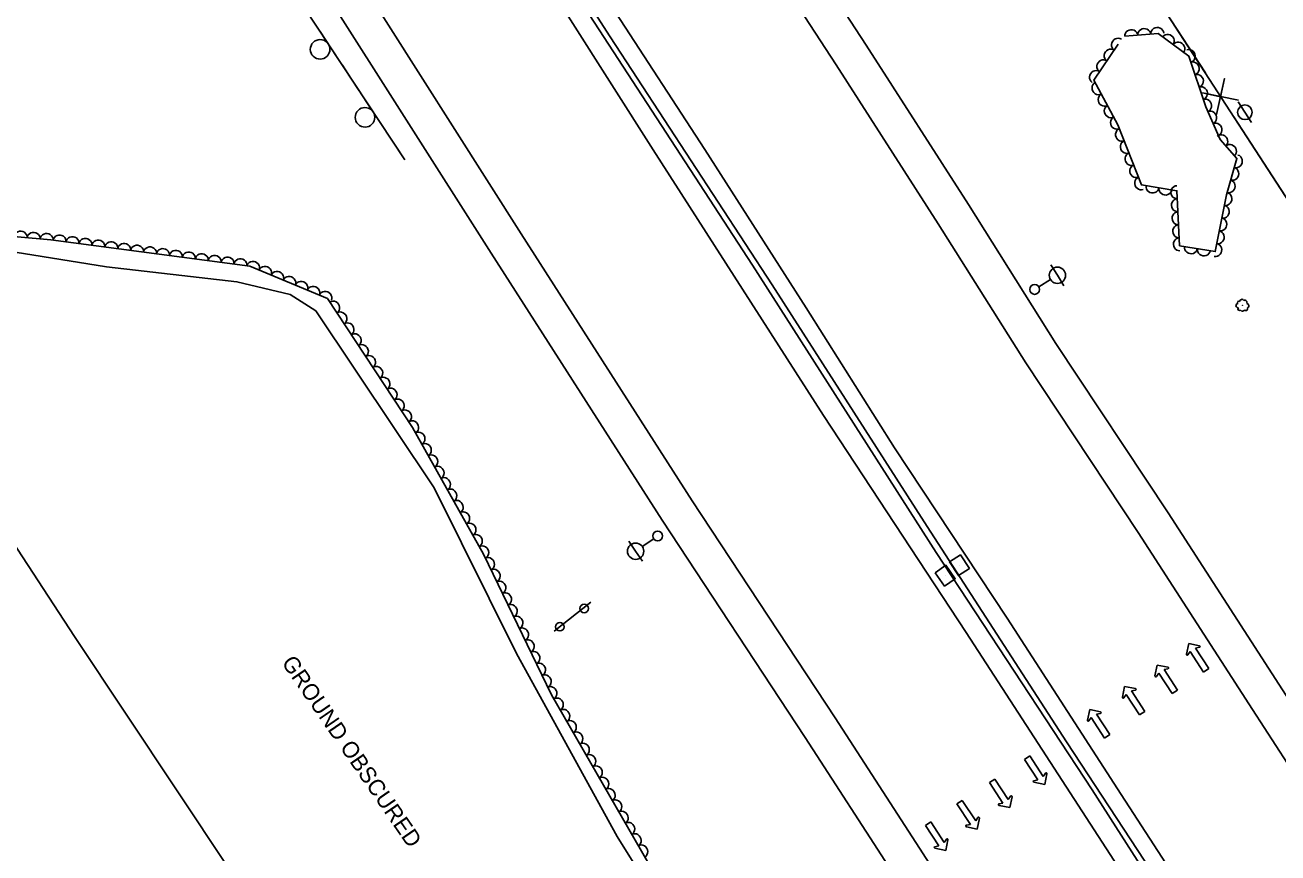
# Model space of a CAD drawing. Extents: x 1746719 to 1766531, y 631721 to 662391.
# Drawn here: x 1759684.8 to 1760069.2, y 641498.8 to 641752.7 of the extents above; entities that cross this region are included whole.
import ezdxf

# ---------------------------------------------------------------- set-up
doc = ezdxf.new("R2010")
doc.units = 0
for name, color, linetype in [('SURVEY - AERIAL SURVEY - Photo Control - Points - Elevations', 7, 'Continuous'), ('SURVEY - AERIAL SURVEY - Photo Control - Points - Locators', 7, 'Continuous'), ('SURVEY - AERIAL SURVEY - Photo Control - Points - Numbers', 7, 'Continuous'), ('SURVEY - AERIAL SURVEY - Photo Control with Text', 7, 'Continuous'), ('SURVEY - CENTERLINE - Existing Roads - Development', 7, 'Continuous'), ('SURVEY - CENTERLINE - Existing Roads Curve Text', 7, 'Continuous'), ('SURVEY - CENTERLINE - Preliminary Curve Text', 7, 'Continuous'), ('SURVEY - CONTROL - Grid', 7, 'Continuous')]:
    doc.layers.add(name, color=color, linetype=linetype)

msp = doc.modelspace()

# ---------------------------------------------------------------- linework, layer by layer
at = {"layer": 'SURVEY - AERIAL SURVEY - Photo Control - Points - Elevations'}
for points in [[(1759256.28, 642562.06), (1759331.34, 642448.21), (1759372.09, 642386.38), (1759428.32, 642299.79), (1759481.08, 642217.88), (1759538.71, 642129.24), (1759603.54, 642028.16), (1759659.74, 641942.25), (1759711.51, 641861.77), (1759776.52, 641763.39), (1759827.75, 641682.76), (1759880.28, 641600.83), (1759924.14, 641534.16), (1759977.94, 641451.1), (1760016.39, 641391.3), (1760062.96, 641319.36), (1760103.56, 641256.45), (1760143.11, 641194.73), (1760191.91, 641118.87), (1760244.47, 641040.54), (1760278.02, 640988.87), (1760344.17, 640886.4)], [(1759271.68, 642558.69), (1759340.52, 642454.26), (1759381.29, 642392.41), (1759437.55, 642305.76), (1759490.31, 642223.86), (1759547.95, 642135.2), (1759612.77, 642034.14), (1759668.97, 641948.23), (1759720.72, 641867.78), (1759785.75, 641769.38), (1759837.02, 641688.68), (1759889.51, 641606.82), (1759933.35, 641540.17), (1759987.18, 641457.06), (1760025.63, 641397.26), (1760072.2, 641325.33), (1760112.81, 641262.4), (1760152.37, 641200.67), (1760201.11, 641124.91), (1760253.65, 641046.61), (1760287.26, 640994.85), (1760353.41, 640892.37)], [(1759339.73, 642542.67), (1759380.59, 642480.68), (1759421.46, 642418.69), (1759477.86, 642331.83), (1759530.61, 642249.94), (1759588.28, 642161.24), (1759653.06, 642060.23), (1759709.23, 641974.36), (1759760.93, 641894), (1759826.04, 641795.48), (1759877.48, 641714.5), (1759929.76, 641632.96), (1759973.54, 641566.41), (1760027.51, 641483.09), (1760065.96, 641423.28), (1760112.51, 641351.39), (1760153.19, 641288.36), (1760192.76, 641226.6), (1760241.22, 641151.27), (1760293.71, 641073.05), (1760327.55, 641020.94), (1760393.74, 640918.4)], [(1759649.07, 642091.68), (1759686.79, 642032.95), (1759716.7, 641987.2), (1759751.66, 641932.46), (1759795.99, 641863.79), (1759827.24, 641815.11), (1759866.04, 641756.45), (1759893.31, 641714.53), (1759924.46, 641666), (1759951.54, 641623.05), (1759986.16, 641570.79), (1760021.11, 641516.73), (1760049.81, 641472.4), (1760081.63, 641423.88), (1760117.03, 641367.86), (1760151.23, 641315.54), (1760184.39, 641264.09), (1760220.08, 641208.95), (1760253.71, 641157.15), (1760284.42, 641109.9), (1760319.58, 641055.54), (1760351.26, 641006.23), (1760381.49, 640960.02), (1760404.24, 640925.21)], [(1759915.38, 641788.81), (1759942.87, 641746.55), (1759974.24, 641697.67), (1760001.09, 641655.07), (1760035.52, 641603.1), (1760070.64, 641548.78), (1760099.24, 641504.61), (1760131.24, 641455.82), (1760166.66, 641399.76), (1760200.72, 641347.67), (1760233.95, 641296.1), (1760269.59, 641241.05), (1760303.18, 641189.29), (1760333.92, 641142), (1760369.17, 641087.5), (1760400.77, 641038.33), (1760430.87, 640992.31), (1760453.63, 640957.5)], [(1759906.18, 641782.77), (1759933.63, 641740.58), (1759964.96, 641691.76), (1759991.85, 641649.1), (1760026.32, 641597.07), (1760061.41, 641542.8), (1760090.03, 641498.61), (1760121.99, 641449.86), (1760157.41, 641393.81), (1760191.49, 641341.68), (1760224.71, 641290.14), (1760260.36, 641235.06), (1760293.96, 641183.3), (1760324.69, 641136.02), (1760359.93, 641081.54), (1760391.54, 641032.35), (1760421.66, 640986.29), (1760444.42, 640951.48)]]:
    msp.add_lwpolyline(points, dxfattribs=at)
at = {"layer": 'SURVEY - AERIAL SURVEY - Photo Control - Points - Locators'}
for p, q in [((1760041.12, 641559.7), (1760041.81, 641563.01)), ((1760041.81, 641563.01), (1760041.12, 641559.7)), ((1760041.81, 641563.01), (1760045.11, 641562.32)), ((1760041.81, 641563.01), (1760045.11, 641562.32)), ((1760045.11, 641561.84), (1760043.9, 641561.61)), ((1760043.9, 641561.61), (1760045.11, 641561.84)), ((1760043.9, 641561.61), (1760048.03, 641555.32)), ((1760048.03, 641555.32), (1760043.9, 641561.61)), ((1760042.26, 641560.53), (1760041.56, 641559.51)), ((1760042.26, 641560.53), (1760041.56, 641559.51)), ((1760046.38, 641554.24), (1760042.26, 641560.53)), ((1760046.38, 641554.24), (1760042.26, 641560.53)), ((1760031.47, 641553.1), (1760032.16, 641556.41)), ((1760032.16, 641556.41), (1760031.47, 641553.1)), ((1760032.61, 641553.93), (1760031.92, 641552.91)), ((1760032.61, 641553.93), (1760031.92, 641552.91)), ((1760032.16, 641556.41), (1760035.47, 641555.72)), ((1760032.16, 641556.41), (1760035.47, 641555.72)), ((1760036.73, 641547.64), (1760032.61, 641553.93)), ((1760036.73, 641547.64), (1760032.61, 641553.93)), ((1760035.46, 641555.24), (1760034.25, 641555.01)), ((1760034.25, 641555.01), (1760035.46, 641555.24)), ((1760034.25, 641555.01), (1760038.38, 641548.72)), ((1760038.38, 641548.72), (1760034.25, 641555.01)), ((1760048.03, 641555.32), (1760046.38, 641554.24)), ((1760046.38, 641554.24), (1760048.03, 641555.32)), ((1760021.46, 641546.54), (1760022.15, 641549.84)), ((1760022.15, 641549.84), (1760021.46, 641546.54)), ((1760022.6, 641547.37), (1760021.91, 641546.35)), ((1760022.6, 641547.37), (1760021.91, 641546.35)), ((1760022.15, 641549.84), (1760025.46, 641549.16)), ((1760022.15, 641549.84), (1760025.46, 641549.16)), ((1760026.72, 641541.08), (1760022.6, 641547.37)), ((1760026.72, 641541.08), (1760022.6, 641547.37)), ((1760025.45, 641548.68), (1760024.24, 641548.45)), ((1760024.24, 641548.45), (1760025.45, 641548.68)), ((1760024.24, 641548.45), (1760028.37, 641542.16)), ((1760028.37, 641542.16), (1760024.24, 641548.45)), ((1760038.38, 641548.72), (1760036.73, 641547.64)), ((1760036.73, 641547.64), (1760038.38, 641548.72)), ((1760010.75, 641539.45), (1760011.44, 641542.75)), ((1760011.44, 641542.75), (1760010.75, 641539.45)), ((1760011.44, 641542.75), (1760014.75, 641542.06)), ((1760011.44, 641542.75), (1760014.75, 641542.06)), ((1760011.89, 641540.27), (1760011.2, 641539.26)), ((1760011.89, 641540.27), (1760011.2, 641539.26)), ((1760016.01, 641533.98), (1760011.89, 641540.27)), ((1760016.01, 641533.98), (1760011.89, 641540.27)), ((1760014.74, 641541.58), (1760013.53, 641541.35)), ((1760013.53, 641541.35), (1760014.74, 641541.58)), ((1760013.53, 641541.35), (1760017.66, 641535.06)), ((1760017.66, 641535.06), (1760013.53, 641541.35)), ((1760028.37, 641542.16), (1760026.72, 641541.08)), ((1760026.72, 641541.08), (1760028.37, 641542.16)), ((1760017.66, 641535.06), (1760016.01, 641533.98)), ((1760016.01, 641533.98), (1760017.66, 641535.06)), ((1759991.42, 641527.44), (1759993.06, 641528.52)), ((1759993.06, 641528.52), (1759991.42, 641527.44)), ((1759995.54, 641521.15), (1759991.42, 641527.44)), ((1759991.42, 641527.44), (1759995.54, 641521.15)), ((1759993.06, 641528.52), (1759997.19, 641522.23)), ((1759993.06, 641528.52), (1759997.19, 641522.23)), ((1759997.19, 641522.23), (1759997.88, 641523.25)), ((1759997.19, 641522.23), (1759997.88, 641523.25)), ((1759998.32, 641523.06), (1759997.63, 641519.75)), ((1759997.63, 641519.75), (1759998.32, 641523.06)), ((1759980.7, 641520.35), (1759982.35, 641521.43)), ((1759982.35, 641521.43), (1759980.7, 641520.35)), ((1759984.83, 641514.06), (1759980.7, 641520.35)), ((1759980.7, 641520.35), (1759984.83, 641514.06)), ((1759982.35, 641521.43), (1759986.47, 641515.14)), ((1759982.35, 641521.43), (1759986.47, 641515.14)), ((1759994.33, 641520.92), (1759995.54, 641521.15)), ((1759995.54, 641521.15), (1759994.33, 641520.92)), ((1759997.63, 641519.75), (1759994.33, 641520.44)), ((1759997.63, 641519.75), (1759994.33, 641520.44)), ((1759986.47, 641515.14), (1759987.17, 641516.15)), ((1759986.47, 641515.14), (1759987.17, 641516.15)), ((1759987.61, 641515.96), (1759986.92, 641512.66)), ((1759986.92, 641512.66), (1759987.61, 641515.96)), ((1759970.69, 641513.78), (1759972.34, 641514.86)), ((1759972.34, 641514.86), (1759970.69, 641513.78)), ((1759974.82, 641507.49), (1759970.69, 641513.78)), ((1759970.69, 641513.78), (1759974.82, 641507.49)), ((1759972.34, 641514.86), (1759976.46, 641508.57)), ((1759972.34, 641514.86), (1759976.46, 641508.57)), ((1759983.62, 641513.83), (1759984.83, 641514.06)), ((1759984.83, 641514.06), (1759983.62, 641513.83)), ((1759986.92, 641512.66), (1759983.62, 641513.35)), ((1759986.92, 641512.66), (1759983.62, 641513.35)), ((1759961.04, 641507.19), (1759962.69, 641508.27)), ((1759962.69, 641508.27), (1759961.04, 641507.19)), ((1759962.69, 641508.27), (1759966.81, 641501.98)), ((1759962.69, 641508.27), (1759966.81, 641501.98)), ((1759976.46, 641508.57), (1759977.16, 641509.59)), ((1759976.46, 641508.57), (1759977.16, 641509.59)), ((1759977.6, 641509.4), (1759976.91, 641506.09)), ((1759976.91, 641506.09), (1759977.6, 641509.4)), ((1759965.17, 641500.9), (1759961.04, 641507.19)), ((1759961.04, 641507.19), (1759965.17, 641500.9)), ((1759973.61, 641507.26), (1759974.82, 641507.49)), ((1759974.82, 641507.49), (1759973.61, 641507.26)), ((1759976.91, 641506.09), (1759973.61, 641506.78)), ((1759976.91, 641506.09), (1759973.61, 641506.78)), ((1759963.96, 641500.67), (1759965.17, 641500.9)), ((1759965.17, 641500.9), (1759963.96, 641500.67)), ((1759967.26, 641499.5), (1759963.96, 641500.19)), ((1759967.26, 641499.5), (1759963.96, 641500.19)), ((1759966.81, 641501.98), (1759967.51, 641502.99)), ((1759966.81, 641501.98), (1759967.51, 641502.99)), ((1759967.95, 641502.81), (1759967.26, 641499.5)), ((1759967.26, 641499.5), (1759967.95, 641502.81))]:
    msp.add_line(p, q, dxfattribs=at)
for points in [[(1759661.89, 641686.19), (1759709.71, 641678.57), (1759749.78, 641673.99), (1759766.09, 641670.05), (1759774.03, 641665.09)], [(1759910.32, 641247.02), (1759855.72, 641330.61), (1759778.79, 641446.62), (1759699.92, 641565.14), (1759631.39, 641669.95)], [(1759774.03, 641665.09), (1759810.29, 641610.78), (1759835.53, 641559.97), (1759866.48, 641503.82), (1759905.29, 641441.52), (1759936.98, 641392.21), (1759970.33, 641331.59), (1759997.67, 641284.96)]]:
    msp.add_lwpolyline(points, dxfattribs=at)
for centre, start, end in [((1760045.07, 641562.08), 280.8054, 78.2537), ((1760045.07, 641562.08), 280.8054, 78.2537), ((1760041.36, 641559.65), 168.2537, 325.7468), ((1760041.36, 641559.65), 168.2537, 325.7468), ((1760035.42, 641555.48), 280.8054, 78.2537), ((1760035.42, 641555.48), 280.8054, 78.2537), ((1760031.71, 641553.05), 168.2537, 325.7468), ((1760031.71, 641553.05), 168.2537, 325.7468), ((1760021.7, 641546.49), 168.2537, 325.7468), ((1760021.7, 641546.49), 168.2537, 325.7468), ((1760025.41, 641548.92), 280.8054, 78.2537), ((1760025.41, 641548.92), 280.8054, 78.2537), ((1760010.99, 641539.4), 168.2537, 325.7468), ((1760010.99, 641539.4), 168.2537, 325.7468), ((1760014.69, 641541.82), 280.8054, 78.2537), ((1760014.69, 641541.82), 280.8054, 78.2537), ((1759998.08, 641523.11), 348.2537, 145.7468), ((1759998.08, 641523.11), 348.2537, 145.7468), ((1759994.38, 641520.68), 100.8054, 258.2537), ((1759994.38, 641520.68), 100.8054, 258.2537), ((1759987.37, 641516.02), 348.2537, 145.7468), ((1759987.37, 641516.02), 348.2537, 145.7468), ((1759983.67, 641513.59), 100.8054, 258.2537), ((1759983.67, 641513.59), 100.8054, 258.2537), ((1759977.36, 641509.45), 348.2537, 145.7468), ((1759977.36, 641509.45), 348.2537, 145.7468), ((1759973.66, 641507.02), 100.8054, 258.2537), ((1759973.66, 641507.02), 100.8054, 258.2537), ((1759964.01, 641500.43), 100.8054, 258.2537), ((1759964.01, 641500.43), 100.8054, 258.2537), ((1759967.71, 641502.86), 348.2537, 145.7468), ((1759967.71, 641502.86), 348.2537, 145.7468)]:
    msp.add_arc(centre, 0.246, start, end, dxfattribs=at)
at = {"layer": 'SURVEY - AERIAL SURVEY - Photo Control - Points - Numbers'}
for points in [[(1759345.56, 642540.12), (1759369.43, 642507.42), (1759376.29, 642498.78), (1759406.04, 642453.59), (1759456.4, 642376.16), (1759516.08, 642283.87), (1759556.82, 642220.43), (1759597.59, 642157.91), (1759654.19, 642071.42), (1759714.99, 641977.18), (1759758.52, 641910), (1759805.91, 641836.88), (1759854.97, 641760.37), (1759907.97, 641679.1), (1759964.38, 641590.9), (1760012.24, 641518.09), (1760081.05, 641410.57), (1760126.05, 641341.92), (1760170.81, 641272.63), (1760237.12, 641169.73), (1760281.11, 641102.87), (1760319.96, 641040.85), (1760359.87, 640980.23), (1760396.33, 640923.21)], [(1759643.49, 642091.23), (1759685.97, 642024.92), (1759725.12, 641963.78), (1759767.21, 641899.68), (1759813.02, 641828.86), (1759864.29, 641749.12), (1759913.96, 641673.03), (1759961.57, 641598.93), (1760004.36, 641532.83), (1760058.79, 641449.82), (1760104.5, 641378.48), (1760159.43, 641293.11), (1760200.94, 641229.52), (1760246.07, 641159.36), (1760287.63, 641096.04), (1760327.89, 641032.95), (1760362.68, 640979.45), (1760398.55, 640924.9)], [(1759593.21, 642029.44), (1759596.82, 642023.81), (1759653.03, 641937.89), (1759704.81, 641857.4), (1759801.29, 641711.41)], [(1759775.29, 641750.75), (1759780.36, 641743.07)], [(1759782.13, 641740.4), (1759784.72, 641736.48)], [(1759784.72, 641736.48), (1759787.31, 641732.56)], [(1759789.07, 641729.89), (1759794.15, 641722.21)], [(1759795.91, 641719.54), (1759798.5, 641715.62)], [(1759798.5, 641715.62), (1759801.09, 641711.7)]]:
    msp.add_lwpolyline(points, dxfattribs=at)
for centre in [(1759775.3, 641745.29), (1759789.08, 641724.44)]:
    msp.add_arc(centre, 3, 146.7274, 146.7134, dxfattribs=at)
at = {"layer": 'SURVEY - AERIAL SURVEY - Photo Control with Text'}
for points in [[(1760022.19, 641749.29), (1760032.4, 641750.13), (1760041.9, 641743.24), (1760047.07, 641727.62), (1760051.44, 641717.65), (1760056.62, 641711.78), (1760053.4, 641700.66), (1760049.97, 641683.27), (1760039.03, 641685.03), (1760038.21, 641701.9), (1760027.32, 641703.68), (1760020.07, 641722.1), (1760012.69, 641735.89), (1760020.19, 641746.93)], [(1759663.03, 641689.47), (1759692.72, 641686.81), (1759753.75, 641678.76), (1759777.55, 641668.87), (1759803.65, 641629.31), (1759825.45, 641590.41), (1759846.33, 641547.25), (1759884, 641481.67), (1759907.38, 641444.09), (1759941.32, 641392.48), (1759962.01, 641354.86), (1759998.08, 641292.26), (1760025.22, 641252.51)]]:
    msp.add_lwpolyline(points, dxfattribs=at)
msp.add_circle((1760058.35, 641666.74), 0.022, dxfattribs=at)
for centre, radius, start, end in [((1760056.93, 641666.65), 0.629, 89.597, 283.0167), ((1760057.23, 641667.6), 0.433, 49.5763, 228.3219), ((1760057.4, 641665.68), 0.479, 132.2156, 309.5348), ((1760058.14, 641667.98), 0.631, 27.4601, 184.249), ((1760058.31, 641665.62), 0.679, 207.5027, 334.3483), ((1760058.99, 641667.61), 0.719, 336.5129, 114.0371), ((1760059.33, 641665.65), 0.527, 217.6616, 32.6619), ((1760059.56, 641666.62), 0.714, 287.4087, 83.2472)]:
    msp.add_arc(centre, radius, start, end, dxfattribs=at)
for centre, major_axis in [((1760024.18, 641749.46), (1.99, 0.16)), ((1760028.17, 641749.78), (1.99, 0.16)), ((1760032.15, 641750.11), (1.99, 0.16)), ((1760035.44, 641747.93), (1.62, -1.17)), ((1760020.06, 641746.74), (1.12, 1.66)), ((1760038.67, 641745.58), (1.62, -1.17)), ((1760015.56, 641740.12), (1.12, 1.66)), ((1760017.81, 641743.43), (1.12, 1.66)), ((1760041.91, 641743.23), (0.63, -1.9)), ((1760013.32, 641736.81), (1.12, 1.66)), ((1760043.16, 641739.43), (0.63, -1.9)), ((1760014.06, 641733.34), (-0.94, 1.76)), ((1760044.42, 641735.63), (0.63, -1.9)), ((1760015.94, 641729.82), (-0.94, 1.76)), ((1760045.67, 641731.84), (0.63, -1.9)), ((1760017.83, 641726.29), (-0.94, 1.76)), ((1760046.93, 641728.04), (0.63, -1.9)), ((1760019.72, 641722.76), (-0.94, 1.76)), ((1760048.5, 641724.36), (0.8, -1.83)), ((1760050.11, 641720.7), (0.8, -1.83)), ((1760021.26, 641719.08), (-0.73, 1.86)), ((1760051.89, 641717.14), (1.32, -1.5)), ((1760022.73, 641715.35), (-0.73, 1.86)), ((1760054.53, 641714.14), (1.32, -1.5)), ((1760024.19, 641711.63), (-0.73, 1.86)), ((1760056.38, 641710.96), (-0.56, -1.92)), ((1760025.65, 641707.91), (-0.73, 1.86)), ((1760055.27, 641707.12), (-0.56, -1.92)), ((1760027.12, 641704.19), (-0.73, 1.86)), ((1760054.16, 641703.28), (-0.56, -1.92)), ((1760030.73, 641703.12), (-1.97, 0.32)), ((1760034.68, 641702.48), (-1.97, 0.32)), ((1760038.23, 641701.47), (-0.1, 2)), ((1760053.16, 641699.41), (-0.39, -1.96)), ((1760038.42, 641697.48), (-0.1, 2)), ((1760052.38, 641695.49), (-0.39, -1.96)), ((1760038.62, 641693.48), (-0.1, 2)), ((1760051.61, 641691.56), (-0.39, -1.96)), ((1759683.41, 641687.64), (1.99, -0.18)), ((1759687.39, 641687.28), (1.99, -0.18)), ((1759691.38, 641686.93), (1.99, -0.18)), ((1759695.35, 641686.46), (1.98, -0.26)), ((1760038.81, 641689.49), (-0.1, 2)), ((1760050.83, 641687.64), (-0.39, -1.96)), ((1759699.32, 641685.94), (1.98, -0.26)), ((1759703.28, 641685.41), (1.98, -0.26)), ((1759707.25, 641684.89), (1.98, -0.26)), ((1759711.21, 641684.37), (1.98, -0.26)), ((1759715.18, 641683.85), (1.98, -0.26)), ((1759719.14, 641683.32), (1.98, -0.26)), ((1759723.11, 641682.8), (1.98, -0.26)), ((1760039.01, 641685.49), (-0.1, 2)), ((1760042.52, 641684.47), (-1.97, 0.32)), ((1760050.06, 641683.71), (-0.39, -1.96)), ((1759727.08, 641682.28), (1.98, -0.26)), ((1759731.04, 641681.76), (1.98, -0.26)), ((1759735.01, 641681.23), (1.98, -0.26)), ((1759738.97, 641680.71), (1.98, -0.26)), ((1759742.94, 641680.19), (1.98, -0.26)), ((1759746.9, 641679.66), (1.98, -0.26)), ((1759750.87, 641679.14), (1.98, -0.26)), ((1760046.46, 641683.83), (-1.97, 0.32)), ((1759754.76, 641678.34), (1.85, -0.77)), ((1759758.45, 641676.81), (1.85, -0.77)), ((1759762.15, 641675.27), (1.85, -0.77)), ((1759765.84, 641673.74), (1.85, -0.77)), ((1759769.54, 641672.2), (1.85, -0.77)), ((1759773.23, 641670.67), (1.85, -0.77)), ((1759776.92, 641669.13), (1.85, -0.77)), ((1759779.38, 641666.1), (1.1, -1.67)), ((1759781.58, 641662.76), (1.1, -1.67)), ((1759783.78, 641659.42), (1.1, -1.67)), ((1759785.99, 641656.08), (1.1, -1.67)), ((1759788.19, 641652.74), (1.1, -1.67)), ((1759790.39, 641649.4), (1.1, -1.67)), ((1759792.6, 641646.06), (1.1, -1.67)), ((1759794.8, 641642.73), (1.1, -1.67)), ((1759797, 641639.39), (1.1, -1.67)), ((1759799.2, 641636.05), (1.1, -1.67)), ((1759801.41, 641632.71), (1.1, -1.67)), ((1759803.61, 641629.37), (1.1, -1.67)), ((1759805.57, 641625.88), (0.98, -1.74)), ((1759807.52, 641622.39), (0.98, -1.74)), ((1759809.48, 641618.9), (0.98, -1.74)), ((1759811.44, 641615.41), (0.98, -1.74)), ((1759813.39, 641611.93), (0.98, -1.74)), ((1759815.35, 641608.44), (0.98, -1.74)), ((1759817.3, 641604.95), (0.98, -1.74)), ((1759819.26, 641601.46), (0.98, -1.74)), ((1759821.21, 641597.97), (0.98, -1.74)), ((1759823.17, 641594.48), (0.98, -1.74)), ((1759825.12, 641590.99), (0.98, -1.74)), ((1759826.9, 641587.41), (0.87, -1.8)), ((1759828.64, 641583.81), (0.87, -1.8)), ((1759830.38, 641580.2), (0.87, -1.8)), ((1759832.13, 641576.6), (0.87, -1.8)), ((1759833.87, 641573), (0.87, -1.8)), ((1759835.61, 641569.4), (0.87, -1.8)), ((1759837.35, 641565.8), (0.87, -1.8)), ((1759839.09, 641562.2), (0.87, -1.8)), ((1759840.84, 641558.6), (0.87, -1.8)), ((1759842.58, 641555), (0.87, -1.8)), ((1759844.32, 641551.4), (0.87, -1.8)), ((1759846.06, 641547.8), (0.87, -1.8)), ((1759848.02, 641544.31), (1, -1.73)), ((1759850.01, 641540.84), (1, -1.73)), ((1759852, 641537.37), (1, -1.73)), ((1759853.99, 641533.9), (1, -1.73)), ((1759855.98, 641530.43), (1, -1.73)), ((1759857.98, 641526.97), (1, -1.73)), ((1759859.97, 641523.5), (1, -1.73)), ((1759861.96, 641520.03), (1, -1.73)), ((1759863.95, 641516.56), (1, -1.73)), ((1759865.95, 641513.09), (1, -1.73)), ((1759867.94, 641509.62), (1, -1.73)), ((1759869.93, 641506.16), (1, -1.73)), ((1759871.92, 641502.69), (1, -1.73)), ((1759873.92, 641499.22), (1, -1.73))]:
    msp.add_ellipse(centre, major_axis=major_axis, ratio=0.940188, start_param=0, end_param=3.141593, dxfattribs=at)
at = {"layer": 'SURVEY - CENTERLINE - Existing Roads - Development'}
for p, q in [((1760059.06, 641725.99), (1760057.04, 641729.15)), ((1760059.06, 641725.99), (1760061.08, 641722.83)), ((1760001.54, 641675.98), (1759999.56, 641679.16)), ((1759995.8, 641672.42), (1759999.41, 641674.66)), ((1760001.54, 641675.98), (1760003.51, 641672.79)), ((1759872.1, 641591.32), (1759869.98, 641594.41)), ((1759877.66, 641595.15), (1759874.16, 641592.74)), ((1759872.1, 641591.32), (1759874.23, 641588.23))]:
    msp.add_line(p, q, dxfattribs=at)
for centre, radius in [((1760059.06, 641725.99), 2.25), ((1760001.54, 641675.98), 2.5), ((1759994.53, 641671.63), 1.5), ((1759878.9, 641596), 1.5), ((1759872.1, 641591.32), 2.5)]:
    msp.add_circle(centre, radius, dxfattribs=at)
at = {"layer": 'SURVEY - CENTERLINE - Existing Roads Curve Text'}
for points in [[(1759665.91, 642312.29), (1759696.99, 642266.05), (1759735.3, 642209.62), (1759771.03, 642158.05), (1759778.53, 642146.83), (1759801.96, 642112.69), (1759837.15, 642061.13), (1759855.16, 642034.2), (1759889.83, 641981.76), (1759925.5, 641924.79), (1759979.94, 641840.44), (1760031.35, 641762.15), (1760084.22, 641680.64), (1760128.36, 641613.89), (1760173.01, 641545.74), (1760208.39, 641490.84), (1760234.81, 641443.36), (1760255.44, 641408.57), (1760291.04, 641352.47), (1760320.06, 641310.32), (1760357.5, 641257.59)], [(1760019.63, 641780), (1760031.35, 641762.15), (1760046.94, 641738.12)], [(1760057.07, 641729.67), (1760046.05, 641731.94), (1760051.59, 641730.77), (1760052.77, 641736.3), (1760050.35, 641725.32)], [(1760055.7, 641724.61), (1760080.95, 641685.68)]]:
    msp.add_lwpolyline(points, dxfattribs=at)
at = {"layer": 'SURVEY - CENTERLINE - Preliminary Curve Text'}
for p, q in [((1759971.47, 641587.02), (1759971.47, 641587.02)), ((1759967.11, 641583.8), (1759967.11, 641583.8))]:
    msp.add_line(p, q, dxfattribs=at)
for points in [[(1759968.42, 641588.02), (1759971.77, 641590.2), (1759974.51, 641586.02), (1759971.16, 641583.83), (1759968.42, 641588.02)], [(1759964.05, 641584.72), (1759967.34, 641586.99), (1759970.18, 641582.87), (1759966.89, 641580.6), (1759964.05, 641584.72)]]:
    msp.add_lwpolyline(points, dxfattribs=at)
at = {"layer": 'SURVEY - CONTROL - Grid'}
msp.add_lwpolyline([(1759858.35, 641575.66), (1759847.15, 641566.82)], dxfattribs=at)
msp.add_lwpolyline([(1759858.35, 641575.66), (1759847.15, 641566.82)], dxfattribs=at)
for centre in [(1759856.34, 641573.75), (1759856.34, 641573.75), (1759848.87, 641568.16)]:
    msp.add_circle(centre, 1.3, dxfattribs=at)

# ---------------------------------------------------------------- texts
at = {"layer": 'SURVEY - AERIAL SURVEY - Photo Control - Points - Locators'}
msp.add_text('GROUND OBSCURED', height=5, rotation=304.5525, dxfattribs=at).set_placement((1759763.3, 641557.12))

doc.saveas('drawing.dxf')
